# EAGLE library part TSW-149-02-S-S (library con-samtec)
THROUGH-HOLE .025" SQ POST HEADER Source: Samtec TSW.pdf
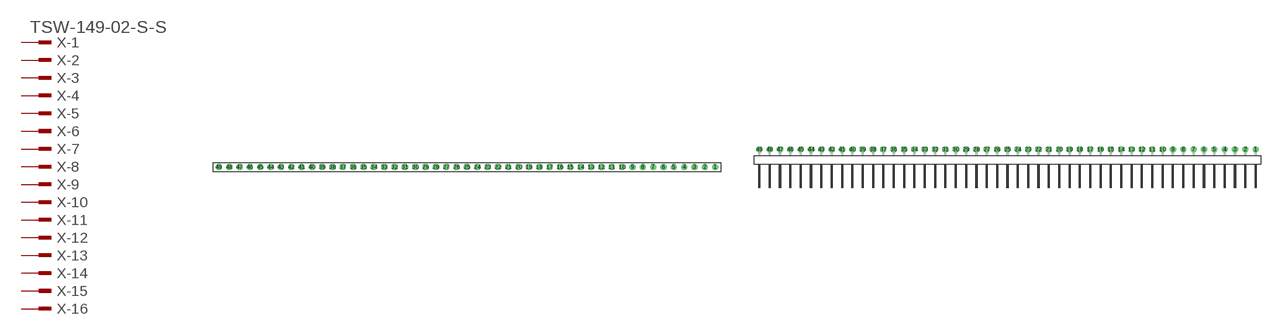
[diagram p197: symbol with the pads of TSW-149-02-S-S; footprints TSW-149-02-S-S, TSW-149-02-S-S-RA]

Designator prefix X; gates -1=MPINV -2=MPIN -3=MPIN -4=MPIN -5=MPIN -6=MPIN -7=MPIN -8=MPIN -9=MPIN -10=MPIN -11=MPIN -12=MPIN -13=MPIN -14=MPIN -15=MPIN -16=MPIN -17=MPIN -18=MPIN -19=MPIN -20=MPIN -21=MPIN -22=MPIN -23=MPIN -24=MPIN -25=MPIN -26=MPIN -27=MPIN -28=MPIN -29=MPIN -30=MPIN -31=MPIN -32=MPIN -33=MPIN -34=MPIN -35=MPIN -36=MPIN -37=MPIN -38=MPIN -39=MPIN -40=MPIN -41=MPIN -42=MPIN -43=MPIN -44=MPIN -45=MPIN -46=MPIN -47=MPIN -48=MPIN -49=MPIN

## TSW-149-02-S-S (OC_FARNELL: unknown; OC_NEWARK: unknown)  [TSW-149-02-S-S]
1  -1:1  pas
2  -2:1  pas
3  -3:1  pas
4  -4:1  pas
5  -5:1  pas
6  -6:1  pas
7  -7:1  pas
8  -8:1  pas
9  -9:1  pas
10  -10:1  pas
11  -11:1  pas
12  -12:1  pas
13  -13:1  pas
14  -14:1  pas
15  -15:1  pas
16  -16:1  pas
17  -17:1  pas
18  -18:1  pas
19  -19:1  pas
20  -20:1  pas
21  -21:1  pas
22  -22:1  pas
23  -23:1  pas
24  -24:1  pas
25  -25:1  pas
26  -26:1  pas
27  -27:1  pas
28  -28:1  pas
29  -29:1  pas
30  -30:1  pas
31  -31:1  pas
32  -32:1  pas
33  -33:1  pas
34  -34:1  pas
35  -35:1  pas
36  -36:1  pas
37  -37:1  pas
38  -38:1  pas
39  -39:1  pas
40  -40:1  pas
41  -41:1  pas
42  -42:1  pas
43  -43:1  pas
44  -44:1  pas
45  -45:1  pas
46  -46:1  pas
47  -47:1  pas
48  -48:1  pas
49  -49:1  pas

## TSW-149-02-S-S-RA (OC_FARNELL: unknown; OC_NEWARK: unknown)  [TSW-149-02-S-S-RA]
Pads as for TSW-149-02-S-S

## Footprint TSW-149-02-S-S (pad centres in mm)
THROUGH-HOLE .025" SQ POST HEADER Source: Samtec TSW.pdf
drill 1 pad 1.5 octagon: 1 60.96,0; 2 58.42,0; 3 55.88,0; 4 53.34,0; 5 50.8,0; 6 48.26,0; 7 45.72,0; 8 43.18,0; 9 40.64,0; 10 38.1,0; 11 35.56,0; 12 33.02,0; 13 30.48,0; 14 27.94,0; 15 25.4,0; 16 22.86,0; 17 20.32,0; 18 17.78,0; 19 15.24,0; 20 12.7,0; 21 10.16,0; 22 7.62,0; 23 5.08,0; 24 2.54,0; 25 0,0; 26 -2.54,0; 27 -5.08,0; 28 -7.62,0; 29 -10.16,0; 30 -12.7,0; 31 -15.24,0; 32 -17.78,0; 33 -20.32,0; 34 -22.86,0; 35 -25.4,0; 36 -27.94,0; 37 -30.48,0; 38 -33.02,0; 39 -35.56,0; 40 -38.1,0; 41 -40.64,0; 42 -43.18,0; 43 -45.72,0; 44 -48.26,0; 45 -50.8,0; 46 -53.34,0; 47 -55.88,0; 48 -58.42,0; 49 -60.96,0

## Footprint TSW-149-02-S-S-RA (pad centres in mm)
THROUGH-HOLE .025" SQ POST HEADER Source: Samtec TSW.pdf
drill 1 pad 1.5 octagon: 1 60.96,1.524; 2 58.42,1.524; 3 55.88,1.524; 4 53.34,1.524; 5 50.8,1.524; 6 48.26,1.524; 7 45.72,1.524; 8 43.18,1.524; 9 40.64,1.524; 10 38.1,1.524; 11 35.56,1.524; 12 33.02,1.524; 13 30.48,1.524; 14 27.94,1.524; 15 25.4,1.524; 16 22.86,1.524; 17 20.32,1.524; 18 17.78,1.524; 19 15.24,1.524; 20 12.7,1.524; 21 10.16,1.524; 22 7.62,1.524; 23 5.08,1.524; 24 2.54,1.524; 25 0,1.524; 26 -2.54,1.524; 27 -5.08,1.524; 28 -7.62,1.524; 29 -10.16,1.524; 30 -12.7,1.524; 31 -15.24,1.524; 32 -17.78,1.524; 33 -20.32,1.524; 34 -22.86,1.524; 35 -25.4,1.524; 36 -27.94,1.524; 37 -30.48,1.524; 38 -33.02,1.524; 39 -35.56,1.524; 40 -38.1,1.524; 41 -40.64,1.524; 42 -43.18,1.524; 43 -45.72,1.524; 44 -48.26,1.524; 45 -50.8,1.524; 46 -53.34,1.524; 47 -55.88,1.524; 48 -58.42,1.524; 49 -60.96,1.524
